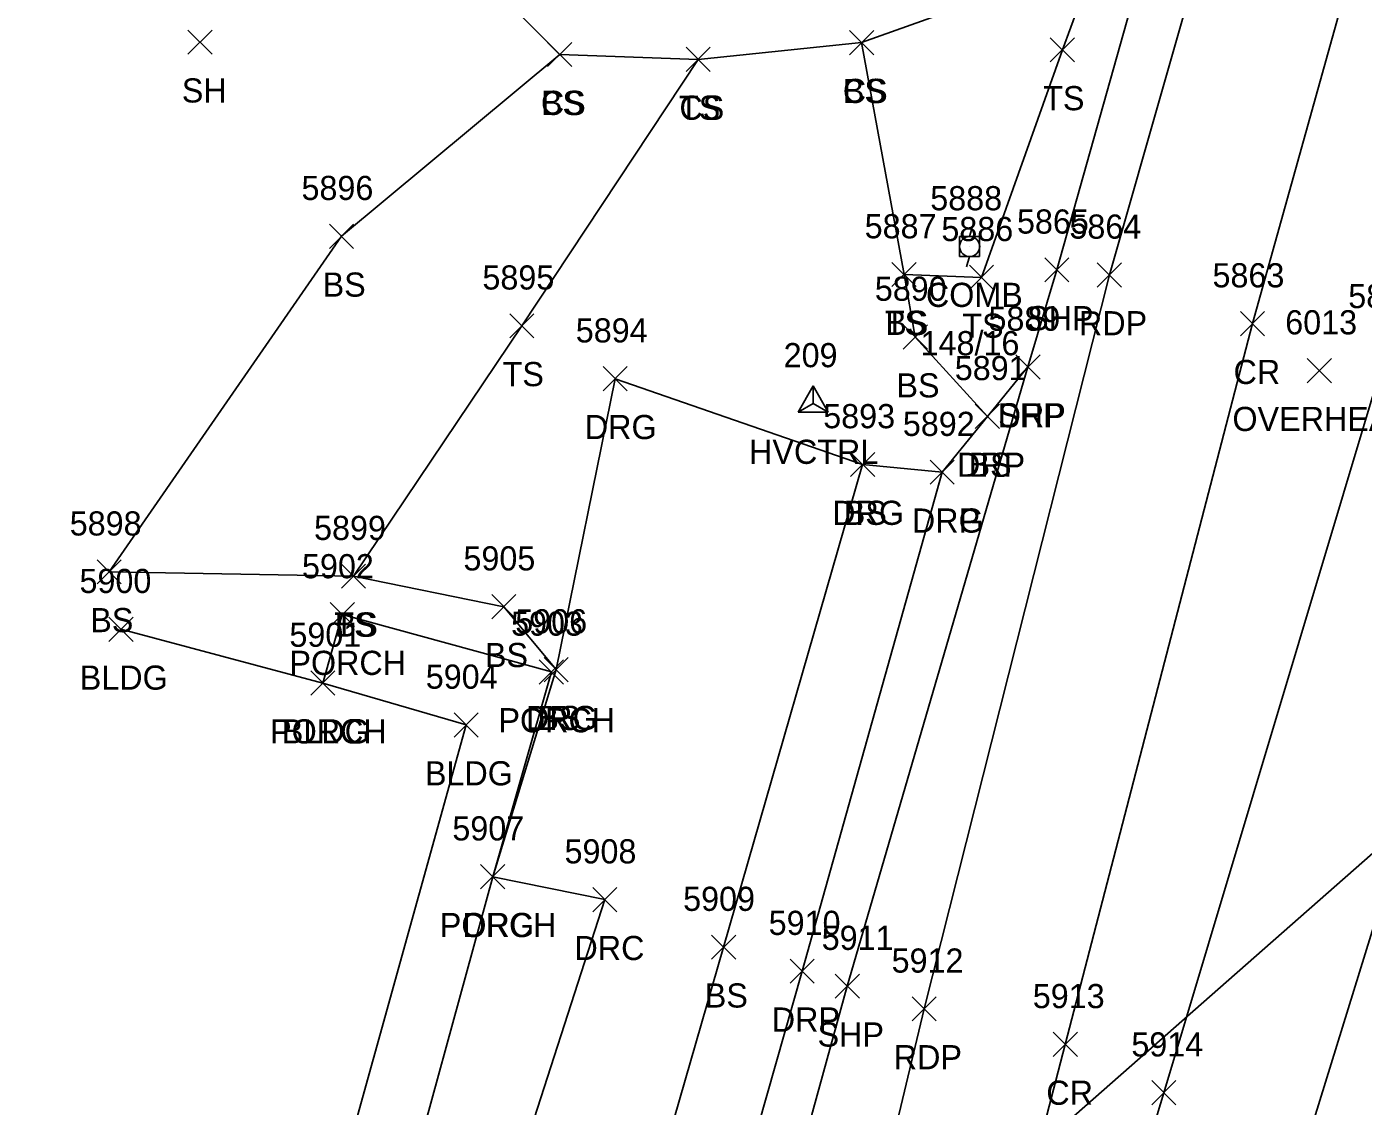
# Model space of a CAD drawing. Extents: x 1443912 to 1445411, y 621446 to 623693.
# Drawn here: x 1444563.4 to 1444674.1, y 622248.9 to 622338.2 of the extents above; entities that cross this region are included whole.
import ezdxf

# ---------------------------------------------------------------- set-up
doc = ezdxf.new("R2010")
doc.units = 0
for name, color, linetype in [('C_A', 7, 'Continuous'), ('C_I', 7, 'Continuous'), ('CPSM', 7, 'Continuous'), ('DCP', 7, 'Continuous'), ('L_A', 7, 'Continuous'), ('L_I', 7, 'Continuous'), ('L_TIC', 7, 'Continuous'), ('LBC', 7, 'Continuous'), ('LBF', 7, 'Continuous'), ('LELB', 7, 'Continuous'), ('P_A', 7, 'Continuous'), ('P_I', 7, 'Continuous'), ('P_TIC', 7, 'Continuous'), ('PET', 7, 'Continuous'), ('PRC', 7, 'Continuous'), ('PSP', 7, 'Continuous'), ('R_A', 7, 'Continuous'), ('R_I', 7, 'Continuous'), ('R_TIC', 7, 'Continuous'), ('RDG', 7, 'Continuous'), ('RDP', 7, 'Continuous'), ('U_A', 7, 'Continuous'), ('U_C', 7, 'Continuous'), ('U_I', 7, 'Continuous'), ('U_TIC', 7, 'Continuous'), ('UP', 7, 'Continuous')]:
    doc.layers.add(name, color=color, linetype=linetype)

msp = doc.modelspace()

# ---------------------------------------------------------------- linework, layer by layer
at = {"layer": 'CPSM'}
for p, q in [((1444627.31, 622306.31), (1444628.56, 622308.48)), ((1444629.81, 622306.31), (1444628.56, 622308.48)), ((1444628.56, 622307.03), (1444628.56, 622308.48)), ((1444627.31, 622306.31), (1444628.56, 622307.03)), ((1444628.56, 622307.03), (1444628.56, 622307.03)), ((1444628.56, 622307.03), (1444629.81, 622306.31)), ((1444627.31, 622306.31), (1444629.81, 622306.31))]:
    msp.add_line(p, q, dxfattribs=at)
at = {"layer": 'DCP'}
msp.add_lwpolyline([(1444682.23, 622276.27), (1444625.81, 622226.66)], dxfattribs=at)
at = {"layer": 'L_TIC'}
for points in [[(1444576.79, 622335.94), (1444578.79, 622337.94)], [(1444578.79, 622335.94), (1444576.79, 622337.94)], [(1444631.57, 622335.9), (1444633.57, 622337.9)], [(1444633.57, 622335.9), (1444631.57, 622337.9)], [(1444631.57, 622335.9), (1444633.57, 622337.9)], [(1444633.57, 622335.9), (1444631.57, 622337.9)], [(1444606.57, 622334.91), (1444608.57, 622336.91)], [(1444608.57, 622334.91), (1444606.57, 622336.91)], [(1444606.57, 622334.91), (1444608.57, 622336.91)], [(1444608.57, 622334.91), (1444606.57, 622336.91)], [(1444648.19, 622335.3), (1444650.19, 622337.3)], [(1444650.19, 622335.3), (1444648.19, 622337.3)], [(1444618.04, 622334.51), (1444620.04, 622336.51)], [(1444620.04, 622334.51), (1444618.04, 622336.51)], [(1444618.04, 622334.51), (1444620.04, 622336.51)], [(1444620.04, 622334.51), (1444618.04, 622336.51)], [(1444588.5, 622319.87), (1444590.5, 622321.87)], [(1444590.5, 622319.87), (1444588.5, 622321.87)], [(1444635.08, 622316.7), (1444637.08, 622318.7)], [(1444637.08, 622316.7), (1444635.08, 622318.7)], [(1444635.08, 622316.7), (1444637.08, 622318.7)], [(1444637.08, 622316.7), (1444635.08, 622318.7)], [(1444641.49, 622316.47), (1444643.49, 622318.47)], [(1444643.49, 622316.47), (1444641.49, 622318.47)], [(1444603.43, 622312.46), (1444605.43, 622314.46)], [(1444605.43, 622312.46), (1444603.43, 622314.46)], [(1444636.01, 622311.53), (1444638.01, 622313.53)], [(1444638.01, 622311.53), (1444636.01, 622313.53)], [(1444641.98, 622304.96), (1444643.98, 622306.96)], [(1444643.98, 622304.96), (1444641.98, 622306.96)], [(1444631.65, 622300.98), (1444633.65, 622302.98)], [(1444633.65, 622300.98), (1444631.65, 622302.98)], [(1444569.26, 622292.1), (1444571.26, 622294.1)], [(1444571.26, 622292.1), (1444569.26, 622294.1)], [(1444589.5, 622291.73), (1444591.5, 622293.73)], [(1444591.5, 622291.73), (1444589.5, 622293.73)], [(1444589.5, 622291.73), (1444591.5, 622293.73)], [(1444591.5, 622291.73), (1444589.5, 622293.73)], [(1444588.57, 622288.56), (1444590.57, 622290.56)], [(1444590.57, 622288.56), (1444588.57, 622290.56)], [(1444601.94, 622289.21), (1444603.94, 622291.21)], [(1444603.94, 622289.21), (1444601.94, 622291.21)], [(1444570.24, 622287.34), (1444572.24, 622289.34)], [(1444572.24, 622287.34), (1444570.24, 622289.34)], [(1444606.28, 622284), (1444608.28, 622286)], [(1444608.28, 622284), (1444606.28, 622286)], [(1444586.96, 622282.89), (1444588.96, 622284.89)], [(1444588.96, 622282.89), (1444586.96, 622284.89)], [(1444586.96, 622282.89), (1444588.96, 622284.89)], [(1444588.96, 622282.89), (1444586.96, 622284.89)], [(1444605.88, 622283.81), (1444607.88, 622285.81)], [(1444607.88, 622283.81), (1444605.88, 622285.81)], [(1444598.82, 622279.42), (1444600.82, 622281.42)], [(1444600.82, 622279.42), (1444598.82, 622281.42)], [(1444601.02, 622266.86), (1444603.02, 622268.86)], [(1444603.02, 622266.86), (1444601.02, 622268.86)], [(1444620.14, 622261.03), (1444622.14, 622263.03)], [(1444622.14, 622261.03), (1444620.14, 622263.03)]]:
    msp.add_lwpolyline(points, dxfattribs=at)
at = {"layer": 'LBC'}
msp.add_lwpolyline([(1444571.24, 622288.34), (1444587.96, 622283.89), (1444599.82, 622280.42), (1444588.2, 622238.64), (1444586.1, 622230.2), (1444579.19, 622204.42), (1444578.25, 622202.21), (1444553.22, 622207.94), (1444553.42, 622209.24), (1444530.69, 622215.06)], dxfattribs=at)
at = {"layer": 'LBF'}
msp.add_lwpolyline([(1444587.96, 622283.89), (1444589.57, 622289.56), (1444606.88, 622284.81), (1444602.02, 622267.86), (1444593.66, 622237.34), (1444588.2, 622238.64)], dxfattribs=at)
at = {"layer": 'LELB'}
for points in [[(1444651.97, 622343.83), (1444632.57, 622336.9), (1444619.04, 622335.51), (1444607.57, 622335.91), (1444593.36, 622350.11), (1444584.8, 622366.91), (1444584.49, 622387.11), (1444584.48, 622405.65)], [(1444663.04, 622380.28), (1444651.97, 622343.83), (1444649.19, 622336.3), (1444642.49, 622317.47), (1444636.08, 622317.7)], [(1444632.57, 622336.9), (1444636.08, 622317.7), (1444637.01, 622312.53), (1444642.98, 622305.96)], [(1444607.57, 622335.91), (1444589.5, 622320.87), (1444570.26, 622293.1), (1444590.5, 622292.73), (1444602.94, 622290.21), (1444607.28, 622285)], [(1444619.04, 622335.51), (1444604.43, 622313.46), (1444590.5, 622292.73)], [(1444632.65, 622301.98), (1444621.14, 622262.03), (1444607.9, 622216.16), (1444601.86, 622188.05), (1444585.99, 622134.3), (1444576.44, 622101.07), (1444565.66, 622076.68), (1444562.93, 622059.13), (1444545.54, 622046.15), (1444545.6, 622027.09), (1444542.78, 622003.02), (1444539.57, 621991.69), (1444533.95, 621966.13), (1444520.51, 621915.8), (1444501.3, 621868.27), (1444484.56, 621807.34), (1444475.47, 621756.73), (1444466.25, 621719.25), (1444448.38, 621716.17)]]:
    msp.add_lwpolyline(points, dxfattribs=at)
at = {"layer": 'P_TIC'}
for points in [[(1444647.73, 622317.09), (1444649.73, 622319.09)], [(1444649.73, 622317.09), (1444647.73, 622319.09)], [(1444652.08, 622316.67), (1444654.08, 622318.67)], [(1444654.08, 622316.67), (1444652.08, 622318.67)], [(1444663.93, 622312.64), (1444665.93, 622314.64)], [(1444665.93, 622312.64), (1444663.93, 622314.64)], [(1444645.34, 622309.05), (1444647.34, 622311.05)], [(1444647.34, 622309.05), (1444645.34, 622311.05)], [(1444630.38, 622257.8), (1444632.38, 622259.8)], [(1444632.38, 622257.8), (1444630.38, 622259.8)], [(1444636.74, 622255.92), (1444638.74, 622257.92)], [(1444638.74, 622255.92), (1444636.74, 622257.92)], [(1444648.43, 622252.98), (1444650.43, 622254.98)], [(1444650.43, 622252.98), (1444648.43, 622254.98)], [(1444656.59, 622248.98), (1444658.59, 622250.98)], [(1444658.59, 622248.98), (1444656.59, 622250.98)]]:
    msp.add_lwpolyline(points, dxfattribs=at)
at = {"layer": 'PET'}
for points in [[(1444623.48, 622089.5), (1444632.2, 622118.09), (1444643.37, 622155.41), (1444656.28, 622199.74), (1444664.4, 622229.62), (1444679.43, 622278.16), (1444690.09, 622315.58), (1444698.44, 622345.72), (1444710.36, 622388.15), (1444723.31, 622433.67), (1444734.7, 622474.11), (1444754.07, 622543.94), (1444762.27, 622574.66), (1444773.16, 622611.58)], [(1444707.78, 622511.05), (1444700.03, 622482.58), (1444691.73, 622453.67), (1444679.73, 622411.23), (1444667.69, 622368.84), (1444653.08, 622317.67), (1444637.74, 622256.92), (1444626.42, 622209.58), (1444619.02, 622182.67), (1444605.37, 622130.08), (1444589.4, 622078.61), (1444578.44, 622026.86), (1444565.52, 621990.05), (1444556.87, 621958.17), (1444542.16, 621907.74), (1444529.8, 621863.07), (1444511.99, 621799.88), (1444498.16, 621751.76), (1444483.13, 621697.3), (1444470.84, 621653.16), (1444463.41, 621627.34), (1444449.07, 621575.52), (1444430.26, 621508.83), (1444421.17, 621471.46)]]:
    msp.add_lwpolyline(points, dxfattribs=at)
at = {"layer": 'PRC'}
for points in [[(1444864.1, 623005.34), (1444851.39, 622950.16), (1444837.25, 622893.61), (1444822.84, 622838.02), (1444810.34, 622792.94), (1444799.32, 622750.35), (1444788.05, 622712.65), (1444779.51, 622680.27), (1444771.55, 622651.63), (1444762.01, 622615.65), (1444752.75, 622584.12), (1444739.92, 622538.84), (1444733.6, 622516.91), (1444722.13, 622475.76), (1444713.59, 622446.41), (1444702.09, 622404.55), (1444689.87, 622361.08), (1444676.17, 622311.92), (1444657.59, 622249.98), (1444643.66, 622204.01), (1444635.38, 622177.66), (1444620.59, 622126.88), (1444604.97, 622075.74)], [(1444846.73, 622950.74), (1444829.37, 622896.11), (1444814.12, 622840.53), (1444801.7, 622795.63), (1444790.08, 622753.54), (1444778.65, 622716.11), (1444769.12, 622683.18), (1444760.94, 622654.81), (1444750.77, 622619.03), (1444741.67, 622586.01), (1444729.73, 622541.23), (1444723.42, 622520.39), (1444711.77, 622478.97), (1444703.65, 622449.63), (1444691.66, 622407.43), (1444679.51, 622365.85), (1444664.93, 622313.64), (1444649.43, 622253.98), (1444637.04, 622206.21), (1444631.31, 622178.74), (1444618.32, 622127.38), (1444604.97, 622075.74)]]:
    msp.add_lwpolyline(points, dxfattribs=at)
at = {"layer": 'PSP'}
msp.add_lwpolyline([(1444708.02, 622525.06), (1444703.26, 622510.63), (1444694.99, 622483.8), (1444687.65, 622455.43), (1444679.42, 622427.15), (1444669.36, 622395.79), (1444665.29, 622376.89), (1444648.73, 622318.09), (1444646.34, 622310.05), (1444631.38, 622258.8), (1444618.63, 622212.47), (1444610.54, 622185.48), (1444596.17, 622132.46), (1444585.6, 622096.58)], dxfattribs=at)
at = {"layer": 'R_TIC'}
for points in [[(1444645.34, 622309.05), (1444647.34, 622311.05)], [(1444647.34, 622309.05), (1444645.34, 622311.05)], [(1444611.16, 622308.08), (1444613.16, 622310.08)], [(1444613.16, 622308.08), (1444611.16, 622310.08)], [(1444641.98, 622304.96), (1444643.98, 622306.96)], [(1444643.98, 622304.96), (1444641.98, 622306.96)], [(1444631.65, 622300.98), (1444633.65, 622302.98)], [(1444633.65, 622300.98), (1444631.65, 622302.98)], [(1444638.24, 622300.34), (1444640.24, 622302.34)], [(1444640.24, 622300.34), (1444638.24, 622302.34)], [(1444638.24, 622300.34), (1444640.24, 622302.34)], [(1444640.24, 622300.34), (1444638.24, 622302.34)], [(1444606.28, 622284), (1444608.28, 622286)], [(1444608.28, 622284), (1444606.28, 622286)], [(1444601.02, 622266.86), (1444603.02, 622268.86)], [(1444603.02, 622266.86), (1444601.02, 622268.86)], [(1444601.02, 622266.86), (1444603.02, 622268.86)], [(1444603.02, 622266.86), (1444601.02, 622268.86)], [(1444610.31, 622264.96), (1444612.31, 622266.96)], [(1444612.31, 622264.96), (1444610.31, 622266.96)], [(1444626.65, 622259.04), (1444628.65, 622261.04)], [(1444628.65, 622259.04), (1444626.65, 622261.04)]]:
    msp.add_lwpolyline(points, dxfattribs=at)
at = {"layer": 'RDG'}
msp.add_lwpolyline([(1444639.24, 622301.34), (1444632.65, 622301.98), (1444612.16, 622309.08), (1444607.28, 622285), (1444602.02, 622267.86)], dxfattribs=at)
at = {"layer": 'RDP'}
for points in [[(1444646.34, 622310.05), (1444642.98, 622305.96), (1444639.24, 622301.34), (1444627.65, 622260.04), (1444614.51, 622213.82), (1444606.96, 622186.79), (1444591.94, 622132.84), (1444574.55, 622074.53), (1444576.22, 622067.8)], [(1444602.02, 622267.86), (1444611.31, 622265.96), (1444601.26, 622234.85), (1444593.66, 622237.34)]]:
    msp.add_lwpolyline(points, dxfattribs=at)
at = {"layer": 'U_TIC'}
for points in [[(1444669.46, 622308.75), (1444671.46, 622310.75)], [(1444671.46, 622308.75), (1444669.46, 622310.75)]]:
    msp.add_lwpolyline(points, dxfattribs=at)
at = {"layer": 'UP'}
for p, q in [((1444641.76, 622321.69), (1444641.51, 622320.85)), ((1444640.68, 622319.19), (1444640.68, 622320.85)), ((1444640.68, 622320.85), (1444642.34, 622320.85)), ((1444642.34, 622320.85), (1444642.34, 622319.19)), ((1444642.34, 622319.19), (1444640.68, 622319.19)), ((1444641.26, 622318.35), (1444641.51, 622319.19)), ((1444641.51, 622320.02), (1444641.51, 622320.02))]:
    msp.add_line(p, q, dxfattribs=at)
msp.add_circle((1444641.51, 622320.02), 0.833, dxfattribs=at)

# ---------------------------------------------------------------- texts
at = {"layer": 'C_A'}
msp.add_text('HVCTRL', height=2, dxfattribs=at).set_placement((1444623.25, 622302.03))
at = {"layer": 'C_I'}
msp.add_text('209', height=2, dxfattribs=at).set_placement((1444626.11, 622310.03))
at = {"layer": 'L_A'}
for s, p in [('SH', (1444576.28, 622331.94)), ('CS', (1444631.01, 622331.9)), ('BS', (1444631.01, 622331.9)), ('CS', (1444606.01, 622330.91)), ('BS', (1444606.01, 622330.91)), ('TS', (1444617.45, 622330.51)), ('CS', (1444617.48, 622330.51)), ('TS', (1444647.6, 622331.3)), ('BS', (1444587.94, 622315.87)), ('TS', (1444634.49, 622312.7)), ('BS', (1444634.52, 622312.7)), ('TS', (1444640.9, 622312.47)), ('TS', (1444602.84, 622308.46)), ('BS', (1444635.45, 622307.53)), ('BS', (1444641.42, 622300.96)), ('BS', (1444631.09, 622296.98)), ('BS', (1444568.7, 622288.1)), ('TS', (1444588.91, 622287.73)), ('BS', (1444588.94, 622287.73)), ('BS', (1444601.38, 622285.21)), ('PORCH', (1444585.19, 622284.56)), ('BLDG', (1444567.83, 622283.34)), ('PORCH', (1444602.5, 622279.81)), ('BS', (1444605.72, 622280)), ('PORCH', (1444583.59, 622278.89)), ('BLDG', (1444584.56, 622278.89)), ('BLDG', (1444596.41, 622275.42)), ('PORCH', (1444597.64, 622262.86)), ('BS', (1444619.58, 622257.03))]:
    msp.add_text(s, height=2, dxfattribs=at).set_placement(p)
at = {"layer": 'L_I'}
for s, p in [('5896', (1444586.19, 622323.87)), ('5887', (1444632.82, 622320.7)), ('5887', (1444632.82, 622320.7)), ('5886', (1444639.17, 622320.47)), ('5895', (1444601.17, 622316.46)), ('5890', (1444633.66, 622315.53)), ('5891', (1444640.28, 622308.96)), ('5893', (1444629.39, 622304.98)), ('5898', (1444567, 622296.1)), ('5899', (1444587.23, 622295.73)), ('5899', (1444587.23, 622295.73)), ('5905', (1444599.6, 622293.21)), ('5902', (1444586.23, 622292.56)), ('5900', (1444567.81, 622291.34)), ('5903', (1444603.54, 622287.81)), ('5906', (1444603.89, 622288)), ('5901', (1444585.19, 622286.89)), ('5901', (1444585.19, 622286.89)), ('5904', (1444596.48, 622283.42)), ('5907', (1444598.68, 622270.86)), ('5909', (1444617.79, 622265.03))]:
    msp.add_text(s, height=2, dxfattribs=at).set_placement(p)
at = {"layer": 'P_A'}
for s, p in [('SHP', (1444646.27, 622313.09)), ('RDP', (1444650.56, 622312.67)), ('CR', (1444663.36, 622308.64)), ('SHP', (1444643.88, 622305.05)), ('SHP', (1444628.92, 622253.8)), ('RDP', (1444635.23, 622251.92)), ('CR', (1444647.86, 622248.98))]:
    msp.add_text(s, height=2, dxfattribs=at).set_placement(p)
at = {"layer": 'P_I'}
for s, p in [('5865', (1444645.43, 622321.09)), ('5864', (1444649.77, 622320.67)), ('5863', (1444661.62, 622316.64)), ('5862', (1444672.86, 622314.92)), ('5889', (1444643.07, 622313.05)), ('5911', (1444629.26, 622261.8)), ('5912', (1444635.05, 622259.92)), ('5913', (1444646.74, 622256.98)), ('5914', (1444654.9, 622252.98))]:
    msp.add_text(s, height=2, dxfattribs=at).set_placement(p)
at = {"layer": 'R_A'}
for s, p in [('DRP', (1444643.83, 622305.05)), ('DRG', (1444609.65, 622304.08)), ('DRP', (1444640.46, 622300.96)), ('DRG', (1444630.13, 622296.98)), ('DRG', (1444636.73, 622296.34)), ('DRP', (1444636.73, 622296.34)), ('DRG', (1444604.77, 622280)), ('DRG', (1444599.51, 622262.86)), ('DRC', (1444599.51, 622262.86)), ('DRC', (1444608.79, 622260.96)), ('DRP', (1444625.13, 622255.04))]:
    msp.add_text(s, height=2, dxfattribs=at).set_placement(p)
at = {"layer": 'R_I'}
for s, p in [('5889', (1444643.07, 622313.05)), ('5894', (1444608.9, 622312.08)), ('5891', (1444640.28, 622308.96)), ('5893', (1444629.39, 622304.98)), ('5892', (1444635.98, 622304.34)), ('5892', (1444635.98, 622304.34)), ('5906', (1444603.89, 622288)), ('5907', (1444598.68, 622270.86)), ('5907', (1444598.68, 622270.86)), ('5908', (1444607.97, 622268.96)), ('5910', (1444624.87, 622263.04))]:
    msp.add_text(s, height=2, dxfattribs=at).set_placement(p)
at = {"layer": 'U_A'}
for s, p in [('COMB', (1444637.89, 622315.02)), ('OVERHEAD', (1444663.27, 622304.75))]:
    msp.add_text(s, height=2, dxfattribs=at).set_placement(p)
at = {"layer": 'U_C'}
msp.add_text('148/16', height=2, dxfattribs=at).set_placement((1444637.45, 622311.02))
at = {"layer": 'U_I'}
for s, p in [('5888', (1444638.25, 622323.02)), ('6013', (1444667.64, 622312.75))]:
    msp.add_text(s, height=2, dxfattribs=at).set_placement(p)

doc.saveas('drawing.dxf')
